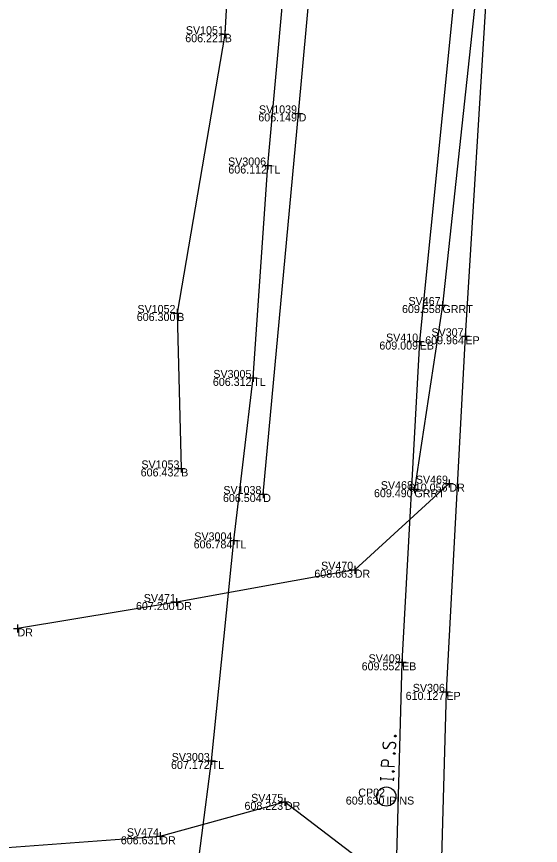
# Model space of a CAD drawing. Extents: x -2 to 1979875, y -2 to 232027.
# Drawn here: x 1978726.8 to 1978759.6, y 231101.8 to 231153.6 of the extents above; entities that cross this region are included whole.
import ezdxf

# ---------------------------------------------------------------- set-up
doc = ezdxf.new("R2010")
doc.units = 0
for name, color, linetype in [('_CIVIL_CONSTRUCTION', 7, 'Continuous'), ('DR_X_Ditch', 7, 'Continuous'), ('GE_P_Alignment', 7, 'Continuous'), ('GE_P_Alignment_1000_Curve_Data', 7, 'Continuous'), ('GE_P_Alignment_1000_Stations', 7, 'Continuous'), ('GE_X_Alignment', 7, 'Continuous'), ('GE_X_Alignment_1000_Stations', 7, 'Continuous'), ('GE_X_Alignment_100_Curve_Data', 7, 'Continuous'), ('GE_X_Alignment_100_Stations', 7, 'Continuous'), ('GE_X_CL', 7, 'Continuous'), ('RW_X_CL', 7, 'Continuous'), ('SC_Scratch1', 7, 'Continuous')]:
    doc.layers.add(name, color=color, linetype=linetype)

msp = doc.modelspace()

# ---------------------------------------------------------------- linework, layer by layer
at = {"layer": 'DR_X_Ditch'}
msp.add_lwpolyline([(1978742.253, 231123.729), (1978744.469, 231147.505), (1978746.577, 231170.723), (1978746.925, 231192.27), (1978746.813, 231208.011), (1978745.79, 231216.793), (1978746.707, 231228.131), (1978745.697, 231237.66), (1978746.077, 231246.913)], dxfattribs=at)
at = {"layer": 'GE_P_Alignment'}
msp.add_lwpolyline([(1978742.352, 231226.722), (1978740.039, 231207.756), (1978741.585, 231191.589), (1978740.923, 231171.641), (1978739.848, 231152.451), (1978736.877, 231135.037), (1978737.12, 231125.328)], dxfattribs=at)
at = {"layer": 'GE_P_Alignment_1000_Curve_Data'}
msp.add_lwpolyline([(1978737.693, 231077.945), (1978737.389, 231087.473), (1978737.815, 231097.725), (1978739.016, 231107.053), (1978740.421, 231120.833), (1978741.632, 231130.981), (1978742.549, 231144.249), (1978743.532, 231155.069), (1978744.086, 231165.377), (1978744.766, 231176.911), (1978744.147, 231186.88), (1978743.211, 231197.568), (1978741.558, 231207.59), (1978737.988, 231217.051), (1978732.124, 231225.954), (1978730.174, 231231.053), (1978733.125, 231254.651), (1978737.318, 231281.706)], dxfattribs=at)
at = {"layer": 'GE_P_Alignment_1000_Stations'}
msp.add_lwpolyline([(1978761.115, 231248.004), (1978759.735, 231223.843), (1978758.381, 231198.86), (1978756.732, 231174.726), (1978755.587, 231155.241), (1978753.463, 231135.535), (1978751.71, 231124.03)], dxfattribs=at)
at = {"layer": 'GE_X_Alignment_1000_Stations'}
msp.add_lwpolyline([(1978748.464, 231019.612), (1978749.988, 231043.472), (1978751.447, 231065.273), (1978752.63, 231084.658), (1978753.33, 231098.021), (1978753.711, 231111.371), (1978754.899, 231133.583), (1978756.265, 231155.604), (1978757.703, 231177.553), (1978759.075, 231200.883), (1978760.359, 231225.015), (1978761.255, 231242.617), (1978761.827, 231253.108)], dxfattribs=at)
at = {"layer": 'GE_X_Alignment_100_Curve_Data'}
for p, q in [((1978739.598, 231152.451), (1978740.098, 231152.451)), ((1978739.848, 231152.701), (1978739.848, 231152.201)), ((1978739.848, 231152.451), (1978739.848, 231152.451)), ((1978744.469, 231147.755), (1978744.469, 231147.255)), ((1978744.219, 231147.505), (1978744.719, 231147.505)), ((1978744.469, 231147.505), (1978744.469, 231147.505)), ((1978742.299, 231144.249), (1978742.799, 231144.249)), ((1978742.549, 231144.499), (1978742.549, 231143.999)), ((1978742.549, 231144.249), (1978742.549, 231144.249)), ((1978753.463, 231135.785), (1978753.463, 231135.285)), ((1978736.877, 231135.287), (1978736.877, 231134.787)), ((1978753.213, 231135.535), (1978753.713, 231135.535)), ((1978753.463, 231135.535), (1978753.463, 231135.535)), ((1978736.627, 231135.037), (1978737.127, 231135.037)), ((1978736.877, 231135.037), (1978736.877, 231135.037)), ((1978754.899, 231133.833), (1978754.899, 231133.333)), ((1978751.788, 231133.252), (1978752.288, 231133.252)), ((1978752.038, 231133.502), (1978752.038, 231133.002)), ((1978752.038, 231133.252), (1978752.038, 231133.252)), ((1978754.649, 231133.583), (1978755.149, 231133.583)), ((1978754.899, 231133.583), (1978754.899, 231133.583)), ((1978741.632, 231131.231), (1978741.632, 231130.731)), ((1978741.382, 231130.981), (1978741.882, 231130.981)), ((1978741.632, 231130.981), (1978741.632, 231130.981)), ((1978737.12, 231125.578), (1978737.12, 231125.078)), ((1978736.87, 231125.328), (1978737.37, 231125.328)), ((1978737.12, 231125.328), (1978737.12, 231125.328)), ((1978753.641, 231124.38), (1978754.141, 231124.38)), ((1978753.891, 231124.63), (1978753.891, 231124.13)), ((1978753.891, 231124.38), (1978753.891, 231124.38)), ((1978742.253, 231123.979), (1978742.253, 231123.479)), ((1978751.46, 231124.03), (1978751.96, 231124.03)), ((1978751.71, 231124.28), (1978751.71, 231123.78)), ((1978751.71, 231124.03), (1978751.71, 231124.03)), ((1978742.003, 231123.729), (1978742.503, 231123.729)), ((1978742.253, 231123.729), (1978742.253, 231123.729)), ((1978740.171, 231120.833), (1978740.671, 231120.833)), ((1978740.421, 231121.083), (1978740.421, 231120.583)), ((1978740.421, 231120.833), (1978740.421, 231120.833)), ((1978747.977, 231119.251), (1978747.977, 231118.751)), ((1978747.727, 231119.001), (1978748.227, 231119.001)), ((1978747.977, 231119.001), (1978747.977, 231119.001)), ((1978736.827, 231117.231), (1978736.827, 231116.731)), ((1978736.577, 231116.981), (1978737.077, 231116.981)), ((1978736.827, 231116.981), (1978736.827, 231116.981)), ((1978726.889, 231115.585), (1978726.889, 231115.085)), ((1978726.639, 231115.335), (1978727.139, 231115.335)), ((1978726.889, 231115.335), (1978726.889, 231115.335)), ((1978750.937, 231113.468), (1978750.937, 231112.968)), ((1978750.687, 231113.218), (1978751.187, 231113.218)), ((1978750.937, 231113.218), (1978750.937, 231113.218)), ((1978753.461, 231111.371), (1978753.961, 231111.371)), ((1978753.711, 231111.621), (1978753.711, 231111.121)), ((1978753.711, 231111.371), (1978753.711, 231111.371)), ((1978739.016, 231107.303), (1978739.016, 231106.803)), ((1978738.766, 231107.053), (1978739.266, 231107.053)), ((1978739.016, 231107.053), (1978739.016, 231107.053)), ((1978743.608, 231104.751), (1978743.608, 231104.251)), ((1978743.358, 231104.501), (1978743.858, 231104.501)), ((1978743.608, 231104.501), (1978743.608, 231104.501)), ((1978735.818, 231102.6), (1978735.818, 231102.1)), ((1978735.568, 231102.35), (1978736.068, 231102.35)), ((1978735.818, 231102.35), (1978735.818, 231102.35))]:
    msp.add_line(p, q, dxfattribs=at)
at = {"layer": 'GE_X_CL'}
for points in [[(1978753.891, 231124.38), (1978747.977, 231119.001), (1978736.827, 231116.981), (1978726.889, 231115.335)], [(1978725.651, 231101.605), (1978735.818, 231102.35), (1978743.608, 231104.501), (1978752.965, 231097.352)]]:
    msp.add_lwpolyline(points, dxfattribs=at)
at = {"layer": 'RW_X_CL'}
for points in [[(1978750.46, 231108.6), (1978750.461, 231108.627), (1978750.475, 231108.643), (1978750.501, 231108.658), (1978750.532, 231108.656), (1978750.556, 231108.638), (1978750.568, 231108.621), (1978750.566, 231108.593), (1978750.553, 231108.578), (1978750.527, 231108.563), (1978750.495, 231108.564), (1978750.471, 231108.582), (1978750.46, 231108.6)], [(1978749.801, 231108.229), (1978749.788, 231108.219), (1978749.774, 231108.203), (1978749.752, 231108.155), (1978749.736, 231108.095), (1978749.734, 231108.051), (1978749.733, 231108.034), (1978749.748, 231107.962), (1978749.782, 231107.899), (1978749.83, 231107.858), (1978749.88, 231107.844), (1978749.917, 231107.841), (1978749.968, 231107.85), (1978750.015, 231107.891), (1978750.221, 231108.183), (1978750.248, 231108.209), (1978750.273, 231108.218), (1978750.312, 231108.227), (1978750.35, 231108.225), (1978750.387, 231108.217), (1978750.412, 231108.21), (1978750.443, 231108.198), (1978750.467, 231108.185), (1978750.485, 231108.173), (1978750.503, 231108.155), (1978750.515, 231108.138), (1978750.526, 231108.115), (1978750.532, 231108.099), (1978750.535, 231108.049), (1978750.531, 231107.972), (1978750.515, 231107.923), (1978750.467, 231107.854), (1978750.427, 231107.812)], [(1978750.397, 231107.51), (1978750.398, 231107.538), (1978750.412, 231107.553), (1978750.438, 231107.568), (1978750.469, 231107.567), (1978750.493, 231107.549), (1978750.505, 231107.531), (1978750.503, 231107.504), (1978750.49, 231107.488), (1978750.464, 231107.473), (1978750.432, 231107.475), (1978750.408, 231107.493), (1978750.397, 231107.51)], [(1978750.456, 231106.684), (1978749.657, 231106.73), (1978749.673, 231106.994), (1978749.681, 231107.022), (1978749.695, 231107.059), (1978749.709, 231107.075), (1978749.722, 231107.091), (1978749.755, 231107.111), (1978749.788, 231107.126), (1978749.839, 231107.134), (1978749.914, 231107.13), (1978749.939, 231107.123), (1978749.976, 231107.109), (1978750.019, 231107.085), (1978750.036, 231107.062), (1978750.048, 231107.045), (1978750.059, 231107.016), (1978750.063, 231106.972), (1978750.047, 231106.708)], [(1978750.332, 231106.388), (1978750.333, 231106.415), (1978750.347, 231106.431), (1978750.373, 231106.446), (1978750.404, 231106.444), (1978750.429, 231106.426), (1978750.44, 231106.409), (1978750.439, 231106.382), (1978750.425, 231106.366), (1978750.399, 231106.351), (1978750.367, 231106.353), (1978750.343, 231106.37), (1978750.332, 231106.388)], [(1978749.607, 231105.861), (1978749.617, 231106.037)], [(1978750.411, 231105.903), (1978749.612, 231105.949)], [(1978750.406, 231105.815), (1978750.416, 231105.991)]]:
    msp.add_lwpolyline(points, dxfattribs=at)
msp.add_circle((1978749.949, 231104.83), 0.6, dxfattribs=at)
at = {"layer": 'SC_Scratch1'}
msp.add_lwpolyline([(1978745.216, 230999.029), (1978746.767, 231023.392), (1978748.222, 231047.741), (1978749.82, 231072.495), (1978750.429, 231094.309), (1978750.937, 231113.218), (1978752.038, 231133.252), (1978754.204, 231154.655), (1978755.357, 231179.613), (1978756.841, 231203.041), (1978757.548, 231221.462), (1978759.078, 231239.679), (1978759.58, 231251.031)], dxfattribs=at)

# ---------------------------------------------------------------- texts
at = {"layer": '_CIVIL_CONSTRUCTION'}
for s, p in [('606.221', (1978737.378, 231151.951)), ('606.149', (1978741.948, 231147.005)), ('606.112', (1978740.073, 231143.749)), ('609.558', (1978750.933, 231135.035)), ('606.300', (1978734.347, 231134.537)), ('609.009', (1978749.517, 231132.752)), ('609.964', (1978752.383, 231133.083)), ('606.312', (1978739.104, 231130.481)), ('606.432', (1978734.592, 231124.828)), ('610.056', (1978751.359, 231123.88)), ('609.490', (1978749.18, 231123.53)), ('606.504', (1978739.737, 231123.229)), ('606.784', (1978737.905, 231120.333)), ('608.663', (1978745.452, 231118.501)), ('607.200', (1978734.297, 231116.481)), ('609.552', (1978748.409, 231112.718)), ('610.127', (1978751.16, 231110.871)), ('607.172', (1978736.488, 231106.553)), ('609.630', (1978747.419, 231104.33)), ('609.630', (1978747.419, 231104.33)), ('609.630', (1978747.419, 231104.33)), ('608.223', (1978741.083, 231104.001)), ('606.631', (1978733.348, 231101.85))]:
    msp.add_text(s, height=0.5, dxfattribs=at).set_placement(p)
at = {"layer": 'GE_X_Alignment'}
for s, p in [('SV1051', (1978737.416, 231152.451)), ('SV1039', (1978741.987, 231147.505)), ('SV3006', (1978740.055, 231144.249)), ('SV467', (1978751.338, 231135.535)), ('SV1052', (1978734.387, 231135.037)), ('SV410', (1978749.934, 231133.252)), ('SV307', (1978752.774, 231133.583)), ('SV3005', (1978739.135, 231130.981)), ('SV1053', (1978734.634, 231125.328)), ('SV469', (1978751.797, 231124.38)), ('SV468', (1978749.607, 231124.03)), ('SV1038', (1978739.762, 231123.729)), ('SV3004', (1978737.944, 231120.833)), ('SV470', (1978745.873, 231119.001)), ('SV471', (1978734.784, 231116.981)), ('SV409', (1978748.843, 231113.218)), ('SV306', (1978751.606, 231111.371)), ('SV3003', (1978736.53, 231107.053)), ('CP02', (1978748.197, 231104.83)), ('CP02', (1978748.197, 231104.83)), ('CP02', (1978748.197, 231104.83)), ('SV475', (1978741.499, 231104.501)), ('SV474', (1978733.729, 231102.35))]:
    msp.add_text(s, height=0.5, dxfattribs=at).set_placement(p)
at = {"layer": 'GE_X_Alignment_100_Stations'}
for s, p in [('B', (1978739.848, 231151.951)), ('D', (1978744.469, 231147.005)), ('TL', (1978742.549, 231143.749)), ('GRRT', (1978753.463, 231135.035)), ('B', (1978736.877, 231134.537)), ('EB', (1978752.038, 231132.752)), ('EP', (1978754.899, 231133.083)), ('TL', (1978741.632, 231130.481)), ('B', (1978737.12, 231124.828)), ('DR', (1978753.891, 231123.88)), ('GRRT', (1978751.71, 231123.53)), ('D', (1978742.253, 231123.229)), ('TL', (1978740.421, 231120.333)), ('DR', (1978747.977, 231118.501)), ('DR', (1978736.827, 231116.481)), ('DR', (1978726.889, 231114.835)), ('EB', (1978750.937, 231112.718)), ('EP', (1978753.711, 231110.871)), ('TL', (1978739.016, 231106.553)), ('IPINS', (1978749.949, 231104.33)), ('IPINS', (1978749.949, 231104.33)), ('IPINS', (1978749.949, 231104.33)), ('DR', (1978743.608, 231104.001)), ('DR', (1978735.818, 231101.85))]:
    msp.add_text(s, height=0.5, dxfattribs=at).set_placement(p)

doc.saveas('drawing.dxf')
